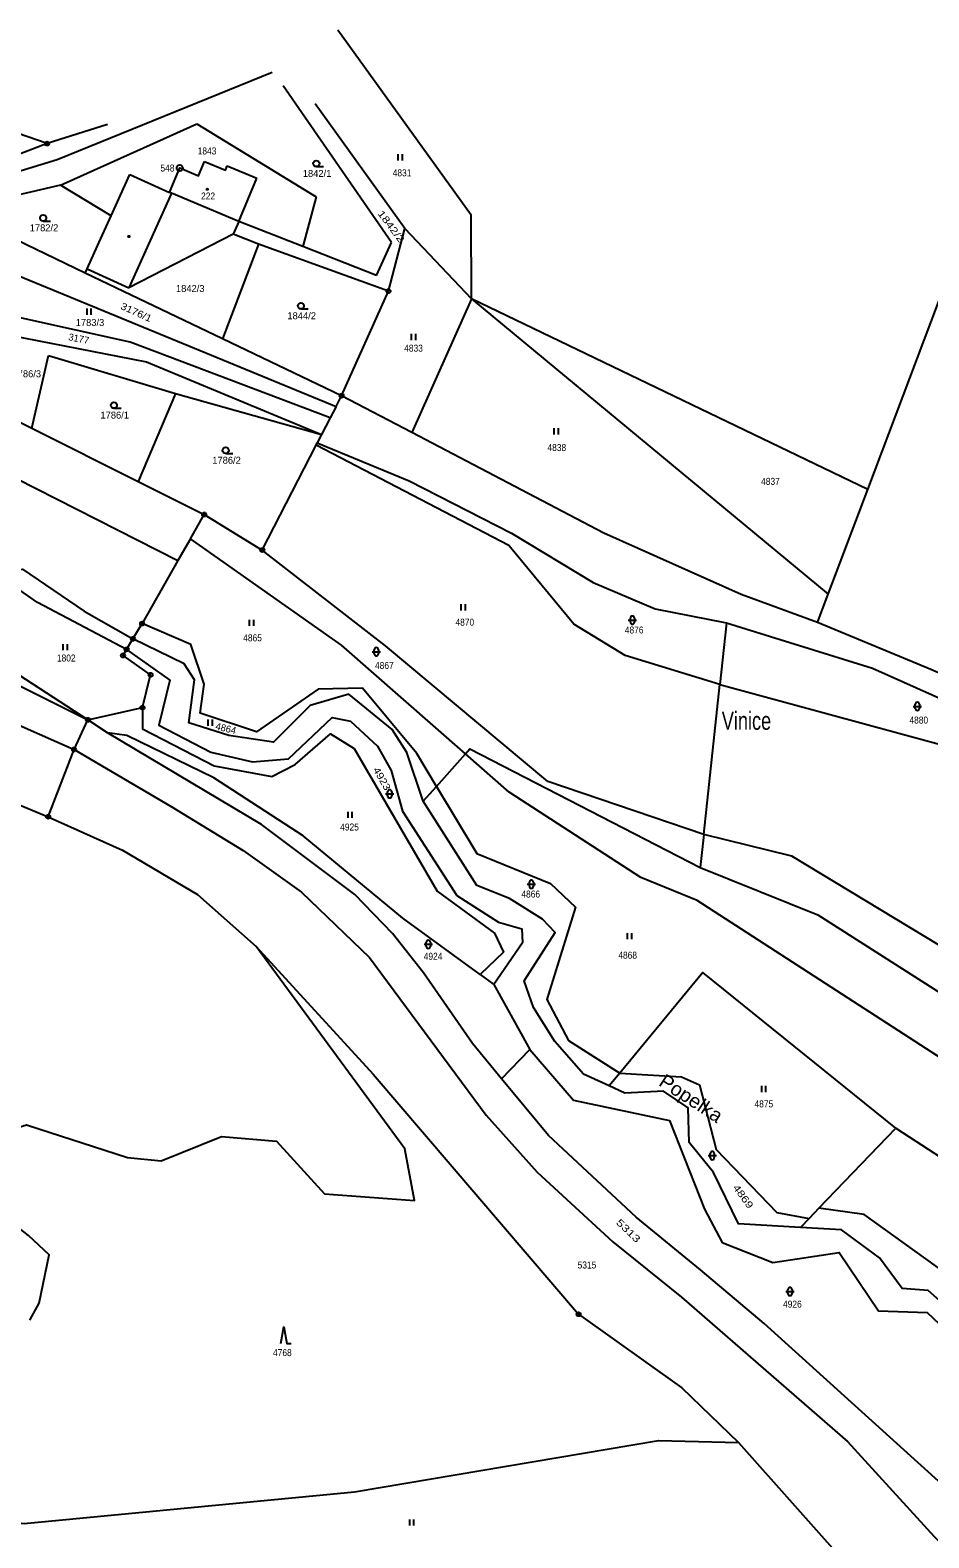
# Model space of a CAD drawing. Extents: x -665688 to -664583, y -1006118 to -1004927.
# Drawn here: x -665410.4 to -665191.6, y -1005400.3 to -1005033.2 of the extents above; entities that cross this region are included whole.
import ezdxf
from ezdxf.enums import TextEntityAlignment as Align

# ---------------------------------------------------------------- set-up
doc = ezdxf.new("R2010")
doc.units = 0
doc.header["$LTSCALE"] = 0.68
for name, color, linetype, lineweight in [('1', 7, 'Continuous', 25), ('24', 7, 'Continuous', 25), ('25', 7, 'Continuous', 25), ('4', 7, 'Continuous', 25)]:
    doc.layers.add(name, color=color, linetype=linetype, lineweight=lineweight)
for name, color, linetype in [('15', 7, 'Continuous'), ('17', 7, 'Continuous'), ('18', 7, 'Continuous'), ('19', 7, 'Continuous')]:
    doc.layers.add(name, color=color, linetype=linetype)

msp = doc.modelspace()

# ---------------------------------------------------------------- linework, layer by layer
at = {"layer": '1'}
for p, q in [((-665351.49, -1005043.52), (-665403.89, -1005064.79)), ((-665322.5, -1005084.89), (-665348.85, -1005046.74)), ((-665319.21, -1005081.44), (-665341.03, -1005051.15)), ((-665403.06, -1005070.95), (-665369.85, -1005055.96)), ((-665369.85, -1005055.96), (-665340.82, -1005073.79)), ((-665403.89, -1005064.79), (-665423.21, -1005070.61)), ((-665362.45, -1005066.19), (-665355.24, -1005069.2)), ((-665390.72, -1005078.37), (-665386.17, -1005068.32)), ((-665386.17, -1005068.32), (-665376.5, -1005072.69)), ((-665376.5, -1005072.69), (-665374.01, -1005066.73)), ((-665359.64, -1005079.73), (-665355.24, -1005069.2)), ((-665403.06, -1005070.95), (-665420.2, -1005074.94)), ((-665390.72, -1005078.37), (-665403.06, -1005070.95)), ((-665340.82, -1005073.79), (-665344.03, -1005085.87)), ((-665397.04, -1005092.31), (-665421.27, -1005080.68)), ((-665394.06, -1005085.73), (-665390.72, -1005078.37)), ((-665359.64, -1005079.73), (-665361.02, -1005082.85)), ((-665361.02, -1005082.85), (-665386.39, -1005095.9)), ((-665354.88, -1005085.26), (-665363.63, -1005108.34)), ((-665326.14, -1005092.91), (-665322.5, -1005084.89)), ((-665422.23, -1005089.3), (-665335.95, -1005124.81)), ((-665396.57, -1005091.3), (-665386.39, -1005095.9)), ((-665363.63, -1005108.34), (-665397.04, -1005092.31)), ((-665206.49, -1005145), (-665303, -1005098.63)), ((-665303, -1005098.63), (-665216.13, -1005170.52)), ((-665430.02, -1005104.62), (-665382.13, -1005113.93)), ((-665337.38, -1005127.59), (-665386.07, -1005109.18)), ((-665334.61, -1005122.2), (-665363.63, -1005108.34)), ((-665410.01, -1005130.09), (-665406, -1005112.43)), ((-665406, -1005112.43), (-665375.07, -1005121.64)), ((-665382.13, -1005113.93), (-665339.48, -1005131.67)), ((-665453.12, -1005122.43), (-665374.45, -1005162.35)), ((-665375.07, -1005121.64), (-665384.16, -1005143.05)), ((-665375.07, -1005121.64), (-665339.48, -1005131.67)), ((-665339.48, -1005131.67), (-665340.52, -1005133.7)), ((-665371.42, -1005157.04), (-665368.06, -1005151.13)), ((-665368.06, -1005151.13), (-665353.92, -1005159.79)), ((-665385.41, -1005181.4), (-665383.19, -1005177.68)), ((-665387.83, -1005185.46), (-665386.94, -1005183.97)), ((-665386.94, -1005183.97), (-665385.41, -1005181.4)), ((-665399.75, -1005208.35), (-665396.36, -1005201.13)), ((-665406.05, -1005224.73), (-665399.75, -1005208.35)), ((-665311.51, -1005217.32), (-665304.45, -1005209.39)), ((-665314.74, -1005220.95), (-665311.51, -1005217.32)), ((-665246.42, -1005229.05), (-665247.28, -1005237.07)), ((-665300.86, -1005263.16), (-665297.53, -1005265.59)), ((-665297.53, -1005265.59), (-665288.78, -1005281.42)), ((-665218.42, -1005320.08), (-665220.77, -1005322.53)), ((-665238, -1005377.08), (-665210.58, -1005407.96))]:
    msp.add_line(p, q, dxfattribs=at)
for points in [[(-665303, -1005098.63), (-665303.06, -1005078.2), (-665335.52, -1005033.17)], [(-665391.59, -1005056.15), (-665406.32, -1005060.8), (-665475.6, -1005036.92)], [(-665406.32, -1005060.8), (-665423.81, -1005067.54), (-665452.92, -1005060.35)], [(-665374.01, -1005066.73), (-665369.44, -1005068.64), (-665367.99, -1005065.18)], [(-665367.99, -1005065.18), (-665362.91, -1005067.3), (-665362.45, -1005066.19)], [(-665326.14, -1005092.91), (-665344.03, -1005085.87), (-665359.64, -1005079.73)], [(-665323.2, -1005096.73), (-665354.88, -1005085.26), (-665361.02, -1005082.85)], [(-665335.95, -1005124.81), (-665334.61, -1005122.2), (-665323.2, -1005096.73), (-665319.21, -1005081.44)], [(-665319.21, -1005081.44), (-665303, -1005098.63), (-665317.51, -1005131.16), (-665334.61, -1005122.2)], [(-665136.5, -1005215.33), (-665140.44, -1005212.3), (-665152.07, -1005205.93), (-665191.17, -1005188.9), (-665218.73, -1005177.39), (-665216.13, -1005170.52), (-665206.49, -1005145), (-665182.51, -1005081.53)], [(-665397.04, -1005092.31), (-665396.57, -1005091.3), (-665394.06, -1005085.73)], [(-665386.07, -1005109.18), (-665426.11, -1005100.32), (-665456.3, -1005108.91)], [(-665432.72, -1005118.7), (-665410.01, -1005130.09), (-665384.16, -1005143.05), (-665368.06, -1005151.13)], [(-665335.95, -1005124.81), (-665337.38, -1005127.59), (-665339.48, -1005131.67)], [(-665514.04, -1005132.26), (-665506.59, -1005136.67), (-665505.17, -1005141.25), (-665507.72, -1005150.19), (-665497.57, -1005156.74), (-665493.78, -1005157.05), (-665483.06, -1005154.9), (-665481.11, -1005150.18), (-665472.97, -1005138.71), (-665469.63, -1005137.92), (-665466.97, -1005139.63), (-665461.25, -1005154), (-665455.88, -1005158.39), (-665443.5, -1005146.6), (-665429.04, -1005144.56), (-665426.68, -1005144.95), (-665423.98, -1005149.89), (-665426.32, -1005161.08), (-665423.25, -1005164.48), (-665412.28, -1005164.4), (-665397.32, -1005174.67), (-665385.41, -1005181.4)], [(-665218.73, -1005177.39), (-665237.36, -1005170.62), (-665270.75, -1005155.68), (-665317.51, -1005131.16)], [(-665386.94, -1005183.97), (-665408.69, -1005172.54), (-665414.61, -1005168.44), (-665425.44, -1005170.25), (-665430.88, -1005164.83), (-665427.9, -1005150.02), (-665429.63, -1005148.23), (-665431.37, -1005148.46), (-665441.2, -1005150.52), (-665453.34, -1005160.14), (-665457.42, -1005161.99), (-665460.34, -1005159.94), (-665463.81, -1005155.49), (-665469.55, -1005144.54), (-665470.65, -1005142.21), (-665477.11, -1005151.29), (-665478.82, -1005156.97), (-665493.22, -1005159.88), (-665499.08, -1005159.69), (-665501.74, -1005158.09), (-665506.28, -1005155.04), (-665511.31, -1005151.51), (-665508.11, -1005139.59), (-665514.96, -1005136.01)], [(-665246.42, -1005229.05), (-665284.37, -1005216.11), (-665323.9, -1005183.08), (-665353.92, -1005159.79), (-665340.79, -1005134.23)], [(-665242.48, -1005192.49), (-665265.59, -1005185.48), (-665278.06, -1005177.86), (-665293.91, -1005158.63), (-665340.79, -1005134.23), (-665340.52, -1005133.7)], [(-665340.52, -1005133.7), (-665318.15, -1005142.94), (-665293.24, -1005155.67), (-665273.34, -1005167.65), (-665258.26, -1005174.06), (-665240.86, -1005177.51), (-665242.48, -1005192.49)], [(-665593.42, -1005154.98), (-665590.17, -1005156.55), (-665581.14, -1005160.82), (-665545.66, -1005172.05), (-665527.86, -1005181.07), (-665527.45, -1005180.2), (-665515.99, -1005181.03), (-665490.32, -1005183.42), (-665458.39, -1005187.75), (-665437.98, -1005192.49), (-665417.3, -1005200.53), (-665399.75, -1005208.35)], [(-665371.42, -1005157.04), (-665374.45, -1005162.35), (-665383.19, -1005177.68)], [(-665304.45, -1005209.39), (-665334.66, -1005182.93), (-665371.42, -1005157.04)], [(-665427.51, -1005185.63), (-665396.36, -1005201.13), (-665419.93, -1005185.83), (-665438.75, -1005181.72), (-665446.06, -1005180.15), (-665454.25, -1005178.14), (-665462.61, -1005176.43), (-665471.68, -1005175.38), (-665480.17, -1005174.3), (-665505.49, -1005171.9)], [(-665311.51, -1005217.32), (-665316.31, -1005209.32), (-665329.52, -1005193.4), (-665340.34, -1005193.63), (-665355.35, -1005204.03), (-665369.03, -1005199.47), (-665368.1, -1005192.4), (-665371.29, -1005182.74), (-665383.19, -1005177.68)], [(-665240.86, -1005177.51), (-665205.31, -1005188.54), (-665150.34, -1005213.14), (-665138.6, -1005220.79)], [(-665386.94, -1005183.97), (-665376.47, -1005191.46), (-665379.14, -1005202.44), (-665366.47, -1005209.01), (-665356.3, -1005211.34), (-665347.56, -1005210.64), (-665336.87, -1005200.59), (-665332.47, -1005201.43), (-665325.83, -1005207.57), (-665322.54, -1005213.43), (-665319.81, -1005223.39), (-665306.55, -1005243.89), (-665296.39, -1005250.38), (-665290.73, -1005252.03), (-665290.53, -1005255.41), (-665297.53, -1005265.59)], [(-665314.74, -1005220.95), (-665318.69, -1005209.09), (-665322.3, -1005203.49), (-665332.84, -1005194.86), (-665342.26, -1005197.65), (-665351.22, -1005206.55), (-665362.06, -1005204.98), (-665371.78, -1005201.87), (-665370.41, -1005191.42), (-665372.97, -1005187.5), (-665385.41, -1005181.4)], [(-665606.44, -1005185.69), (-665588.29, -1005189.45), (-665568.47, -1005193.44), (-665524.68, -1005197.88), (-665491.46, -1005199.28), (-665463.07, -1005202.62), (-665454.32, -1005206.34), (-665437.29, -1005211.76), (-665406.05, -1005224.73)], [(-665383.09, -1005198.15), (-665381.1, -1005190.16), (-665387.83, -1005185.46)], [(-665059.37, -1005342.9), (-665104.09, -1005312.9), (-665124.43, -1005295.1), (-665225.03, -1005234.3), (-665246.42, -1005229.05), (-665242.48, -1005192.49)], [(-665242.48, -1005192.49), (-665138.6, -1005220.79), (-665110.5, -1005240.56)], [(-665300.86, -1005263.16), (-665319.72, -1005249.42), (-665343.99, -1005229.35), (-665365.7, -1005215.27), (-665386.93, -1005204.97), (-665391.62, -1005204.33), (-665396.36, -1005201.13), (-665383.09, -1005198.15)], [(-665383.09, -1005198.15), (-665383.07, -1005203.29), (-665365.66, -1005212.32), (-665351.56, -1005214.91), (-665345.95, -1005212.04), (-665337.29, -1005204.53), (-665331.51, -1005208.1), (-665311.38, -1005242.85), (-665297.37, -1005253.09), (-665295.18, -1005257.7), (-665300.86, -1005263.16)], [(-665295.64, -1005288.54), (-665302.73, -1005279.97), (-665314.65, -1005262.74), (-665322.23, -1005253.19), (-665331.41, -1005243.66), (-665354.15, -1005226.65), (-665391.62, -1005204.33)], [(-665399.75, -1005208.35), (-665376.11, -1005222.26), (-665358.6, -1005232.91), (-665344.4, -1005243.08), (-665327.83, -1005258.99), (-665299.41, -1005297.42), (-665287.03, -1005311.31), (-665268.55, -1005328.24), (-665251.87, -1005341.72), (-665211.4, -1005376.84), (-665190.33, -1005399.99), (-665148.79, -1005443.19), (-665127.68, -1005451.74), (-665121.7, -1005462.65), (-665134.58, -1005458.21)], [(-665304.45, -1005209.39), (-665303.36, -1005208.17), (-665247.28, -1005237.07)], [(-665050.35, -1005378.04), (-665117.56, -1005329.51), (-665248.06, -1005245.09), (-665261.76, -1005239.56), (-665293.79, -1005218.72), (-665304.45, -1005209.39)], [(-665311.51, -1005217.32), (-665301.72, -1005233.64), (-665283.77, -1005241.01), (-665277.65, -1005246.78), (-665284.62, -1005269.25), (-665279.36, -1005279.23), (-665266.87, -1005287.15)], [(-665269.44, -1005290.26), (-665275.72, -1005287.38), (-665282.66, -1005279.45), (-665287.89, -1005271.19), (-665290.12, -1005264.69), (-665282.62, -1005252.89), (-665285.7, -1005249.7), (-665293.77, -1005244.66), (-665301.68, -1005241.43), (-665314.74, -1005220.95)], [(-665406.05, -1005224.73), (-665387.98, -1005232.88), (-665369.69, -1005243.67), (-665355.41, -1005256.31)], [(-665247.28, -1005237.07), (-665218.64, -1005248.65), (-665060.85, -1005349.31)], [(-665429.85, -1005311.87), (-665423.66, -1005303.48), (-665411.3, -1005299.73), (-665386.72, -1005307.69), (-665378.56, -1005308.54), (-665363.85, -1005302.58), (-665350.44, -1005303.75), (-665338.78, -1005316.57), (-665316.9, -1005318.19), (-665319.2, -1005305.57), (-665355.41, -1005256.31)], [(-665355.41, -1005256.31), (-665326.92, -1005287.45), (-665276.91, -1005345.88), (-665251.76, -1005363.82), (-665238, -1005377.08)], [(-665199.64, -1005300.53), (-665246.63, -1005262.62), (-665266.87, -1005287.15), (-665269.44, -1005290.26)], [(-665186.72, -1005388.88), (-665231.73, -1005348.14), (-665247.24, -1005335.03), (-665262.9, -1005322.2), (-665284.22, -1005302.33), (-665295.64, -1005288.54), (-665288.78, -1005281.42)], [(-665288.78, -1005281.42), (-665278.12, -1005293.76), (-665254.75, -1005298.72), (-665246.23, -1005320.3), (-665241.95, -1005328.41), (-665229.65, -1005333.27), (-665213.43, -1005330.83), (-665203.9, -1005345.02), (-665192.06, -1005345.49), (-665170.08, -1005366.25)], [(-665222.91, -1005324.76), (-665237.94, -1005323.88), (-665244.09, -1005311.36), (-665250.01, -1005304.06), (-665250.21, -1005295.65), (-665256.2, -1005291.53), (-665265.61, -1005292.01), (-665269.44, -1005290.26)], [(-665266.87, -1005287.15), (-665251.84, -1005288.06), (-665247.51, -1005290.01), (-665243.45, -1005305.8), (-665228.63, -1005321.1), (-665220.77, -1005322.53), (-665222.91, -1005324.76)], [(-665139.02, -1005367.43), (-665159.72, -1005355.83), (-665207.38, -1005321.62), (-665218.42, -1005320.08), (-665199.64, -1005300.53)], [(-665199.64, -1005300.53), (-665177.42, -1005315.04), (-665123.06, -1005340.35), (-665139.02, -1005367.43)], [(-665410.5, -1005347.29), (-665408.21, -1005343.15), (-665405.83, -1005331.43), (-665410.87, -1005326.68), (-665429.85, -1005311.87)], [(-665100.81, -1005394.75), (-665112.89, -1005388.29), (-665125.42, -1005382.92), (-665146.27, -1005370.65), (-665172.18, -1005357.52), (-665191.77, -1005340.12), (-665198.15, -1005339.57), (-665203.62, -1005332.13), (-665212.87, -1005325.35), (-665222.91, -1005324.76)], [(-665422.54, -1005395.61), (-665411.87, -1005396.87), (-665331.44, -1005389.13), (-665257.43, -1005376.61), (-665238, -1005377.08)]]:
    msp.add_lwpolyline(points, dxfattribs=at)
at = {"layer": '24'}
for centre, radius in [((-665406.32, -1005060.8), 0.5), ((-665406.32, -1005060.8), 0.032), ((-665374, -1005066.75), 0.75), ((-665374, -1005066.75), 0.032), ((-665323.2, -1005096.73), 0.5), ((-665323.2, -1005096.73), 0.032), ((-665334.61, -1005122.2), 0.5), ((-665334.61, -1005122.2), 0.032), ((-665368.06, -1005151.13), 0.5), ((-665368.06, -1005151.13), 0.032), ((-665353.92, -1005159.79), 0.5), ((-665353.92, -1005159.79), 0.032), ((-665383.19, -1005177.68), 0.5), ((-665383.19, -1005177.68), 0.032), ((-665386.94, -1005183.97), 0.5), ((-665386.94, -1005183.97), 0.032), ((-665385.41, -1005181.4), 0.5), ((-665385.41, -1005181.4), 0.032), ((-665387.83, -1005185.46), 0.5), ((-665387.83, -1005185.46), 0.032), ((-665381.1, -1005190.16), 0.5), ((-665381.1, -1005190.16), 0.032), ((-665383.09, -1005198.15), 0.5), ((-665383.09, -1005198.15), 0.032), ((-665396.36, -1005201.13), 0.5), ((-665396.36, -1005201.13), 0.032), ((-665399.75, -1005208.35), 0.5), ((-665399.75, -1005208.35), 0.032), ((-665406.05, -1005224.73), 0.5), ((-665406.05, -1005224.73), 0.032), ((-665276.91, -1005345.88), 0.5), ((-665276.91, -1005345.88), 0.032)]:
    msp.add_circle(centre, radius, dxfattribs=at)
at = {"layer": '25'}
for p, q in [((-665340.78, -1005066.41), (-665339.03, -1005066.41)), ((-665320.817, -1005064.905), (-665320.817, -1005063.405)), ((-665319.783, -1005064.905), (-665319.783, -1005063.405)), ((-665407.27, -1005079.65), (-665405.52, -1005079.65)), ((-665396.587, -1005102.475), (-665396.587, -1005100.975)), ((-665395.553, -1005102.475), (-665395.553, -1005100.975)), ((-665344.53, -1005101.07), (-665342.78, -1005101.07)), ((-665317.607, -1005108.655), (-665317.607, -1005107.155)), ((-665316.573, -1005108.655), (-665316.573, -1005107.155)), ((-665390.05, -1005125.26), (-665388.3, -1005125.26)), ((-665282.857, -1005131.605), (-665282.857, -1005130.105)), ((-665281.823, -1005131.605), (-665281.823, -1005130.105)), ((-665362.82, -1005136.26), (-665361.07, -1005136.26)), ((-665305.497, -1005174.475), (-665305.497, -1005172.975)), ((-665304.463, -1005174.475), (-665304.463, -1005172.975)), ((-665264.31, -1005177.34), (-665264.31, -1005176.34)), ((-665263.31, -1005176.34), (-665263.31, -1005177.34)), ((-665357.007, -1005178.245), (-665357.007, -1005176.745)), ((-665355.973, -1005178.245), (-665355.973, -1005176.745)), ((-665264.81, -1005176.84), (-665262.81, -1005176.84)), ((-665402.367, -1005184.185), (-665402.367, -1005182.685)), ((-665401.333, -1005184.185), (-665401.333, -1005182.685)), ((-665327.16, -1005184.54), (-665325.16, -1005184.54)), ((-665326.66, -1005185.04), (-665326.66, -1005184.04)), ((-665325.66, -1005184.04), (-665325.66, -1005185.04)), ((-665195.43, -1005197.84), (-665193.43, -1005197.84)), ((-665194.93, -1005198.34), (-665194.93, -1005197.34)), ((-665193.93, -1005197.34), (-665193.93, -1005198.34)), ((-665367.077, -1005202.555), (-665367.077, -1005201.055)), ((-665366.043, -1005202.555), (-665366.043, -1005201.055)), ((-665323.9, -1005219.15), (-665321.9, -1005219.15)), ((-665323.4, -1005219.65), (-665323.4, -1005218.65)), ((-665322.4, -1005218.65), (-665322.4, -1005219.65)), ((-665333.047, -1005225.005), (-665333.047, -1005223.505)), ((-665332.013, -1005225.005), (-665332.013, -1005223.505)), ((-665289.4, -1005241.15), (-665287.4, -1005241.15)), ((-665288.9, -1005241.65), (-665288.9, -1005240.65)), ((-665287.9, -1005240.65), (-665287.9, -1005241.65)), ((-665265.017, -1005254.575), (-665265.017, -1005253.075)), ((-665263.983, -1005254.575), (-665263.983, -1005253.075)), ((-665314.5, -1005255.79), (-665312.5, -1005255.79)), ((-665314, -1005256.29), (-665314, -1005255.29)), ((-665313, -1005255.29), (-665313, -1005256.29)), ((-665232.327, -1005291.785), (-665232.327, -1005290.285)), ((-665231.293, -1005291.785), (-665231.293, -1005290.285)), ((-665245.37, -1005307.24), (-665243.37, -1005307.24)), ((-665244.87, -1005307.74), (-665244.87, -1005306.74)), ((-665243.87, -1005306.74), (-665243.87, -1005307.74)), ((-665226.44, -1005340.35), (-665224.44, -1005340.35)), ((-665225.94, -1005340.85), (-665225.94, -1005339.85)), ((-665224.94, -1005339.85), (-665224.94, -1005340.85)), ((-665318.037, -1005397.365), (-665318.037, -1005395.865)), ((-665317.003, -1005397.365), (-665317.003, -1005395.865))]:
    msp.add_line(p, q, dxfattribs=at)
msp.add_lwpolyline([(-665349.42, -1005352.98), (-665348.67, -1005348.98), (-665347.92, -1005352.98), (-665346.92, -1005352.98)], dxfattribs=at)
for centre, radius in [((-665340.78, -1005065.66), 0.75), ((-665367.32, -1005071.91), 0.175), ((-665407.27, -1005078.9), 0.75), ((-665386.4, -1005083.42), 0.175), ((-665344.53, -1005100.32), 0.75), ((-665390.05, -1005124.51), 0.75), ((-665362.82, -1005135.51), 0.75)]:
    msp.add_circle(centre, radius, dxfattribs=at)
for centre, start, end in [((-665263.81, -1005176.34), 0.101, 180.00143), ((-665263.81, -1005177.34), 180.10243, 0.00286), ((-665326.16, -1005184.04), 0.101, 180.00143), ((-665326.16, -1005185.04), 180.10243, 0.00286), ((-665194.43, -1005197.34), 0.101, 180.00143), ((-665194.43, -1005198.34), 180.10243, 0.00286), ((-665322.9, -1005218.65), 0.101, 180.00143), ((-665322.9, -1005219.65), 180.10243, 0.00286), ((-665288.4, -1005240.65), 0.101, 180.00143), ((-665288.4, -1005241.65), 180.10243, 0.00286), ((-665313.5, -1005255.29), 0.101, 180.00143), ((-665313.5, -1005256.29), 180.10243, 0.00286), ((-665244.37, -1005306.74), 0.101, 180.00143), ((-665244.37, -1005307.74), 180.10243, 0.00286), ((-665225.44, -1005339.85), 0.101, 180.00143), ((-665225.44, -1005340.85), 180.10243, 0.00286)]:
    msp.add_arc(centre, 0.5, start, end, dxfattribs=at)
at = {"layer": '4'}
msp.add_line((-665376.05, -1005072.89), (-665386.39, -1005095.9), dxfattribs=at)
msp.add_lwpolyline([(-665359.64, -1005079.73), (-665376.05, -1005072.89), (-665376.5, -1005072.69)], dxfattribs=at)

# ---------------------------------------------------------------- texts
at = {"layer": '15', "width": 0.75}
msp.add_text('Vinice', height=4.4, dxfattribs=at).set_placement((-665236.0295, -1005203.56), align=Align.CENTER)
at = {"layer": '15', "width": 1.05}
msp.add_text('Popelka', height=3.4, rotation=326.703, dxfattribs=at).set_placement((-665250.4263, -1005294.7148), align=Align.CENTER)
at = {"layer": '17', "width": 0.9}
msp.add_text('548', height=1.7, dxfattribs=at).set_placement((-665375.3, -1005067.6), align=Align.RIGHT)
at = {"layer": '18', "width": 0.9}
for s, p in [('1843', (-665367.3695, -1005063.44)), ('4831', (-665319.8895, -1005068.77)), ('4833', (-665317.0995, -1005111.46)), ('4838', (-665282.2095, -1005135.66)), ('4837', (-665230.1895, -1005143.9)), ('4870', (-665304.6095, -1005178.2)), ('4865', (-665356.2895, -1005182)), ('4876', (-665263.3795, -1005180.1)), ('1802', (-665401.6495, -1005186.92)), ('4867', (-665324.1995, -1005188.73)), ('4880', (-665194.0795, -1005202.03)), ('4925', (-665332.6795, -1005228.08)), ('4866', (-665288.5695, -1005244.4)), ('4924', (-665312.3395, -1005259.56)), ('4868', (-665264.9595, -1005259.3)), ('4875', (-665231.7995, -1005295.5)), ('5315', (-665274.8695, -1005334.74)), ('4926', (-665224.8595, -1005344.26)), ('4768', (-665349.0295, -1005356.08))]:
    msp.add_text(s, height=1.7, dxfattribs=at).set_placement(p, align=Align.CENTER)
at = {"layer": '18'}
for s, p in [('1842/1', (-665340.5795, -1005068.91)), ('1782/2', (-665407.0695, -1005082.15)), ('1842/3', (-665371.4595, -1005096.93)), ('1844/2', (-665344.3295, -1005103.57)), ('1783/3', (-665395.8695, -1005105.21)), ('1786/3', (-665411.2495, -1005117.7)), ('1786/1', (-665389.8495, -1005127.76)), ('1786/2', (-665362.6195, -1005138.76))]:
    msp.add_text(s, height=1.7, dxfattribs=at).set_placement(p, align=Align.CENTER)
for s, rotation, width, p in [('1842/2', 307.002, 1.3, (-665323.2269, -1005081.4719)), ('3176/1', 335.703, 1.15, (-665384.9422, -1005102.6437)), ('4923', 299.702, 1.2, (-665325.528, -1005215.8778)), ('4869', 306.202, 1.3, (-665237.5154, -1005317.7)), ('5313', 316.203, 1.4, (-665265.3833, -1005326.1622))]:
    msp.add_text(s, height=1.7, rotation=rotation, dxfattribs=dict(at, width=width)).set_placement(p, align=Align.CENTER)
for s, rotation, p in [('3177', 348.803, (-665398.7591, -1005109.1375)), ('4864', 346.503, (-665362.9729, -1005204.0323))]:
    msp.add_text(s, height=1.7, rotation=rotation, dxfattribs=at).set_placement(p, align=Align.CENTER)
at = {"layer": '19', "width": 0.9}
msp.add_text('222', height=1.7, dxfattribs=at).set_placement((-665367.1195, -1005074.41), align=Align.CENTER)

doc.saveas('drawing.dxf')
